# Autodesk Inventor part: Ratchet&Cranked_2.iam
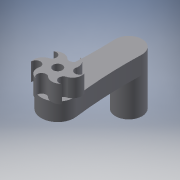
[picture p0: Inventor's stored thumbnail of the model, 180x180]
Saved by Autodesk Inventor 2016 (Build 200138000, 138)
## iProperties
Created: 2013-11
Part Number: Ratchet&Cranked_2.iam
Material: Generic
Document SubType Name: Modeling
Designer: 603839
Density: 1 g/cm^3
Appearance: Default
Mass: 4.07709 g
Surface Area: 25.4645 cm^2
Volume: 4.07709 cm^3
Author: 603839
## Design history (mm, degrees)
sketch "Sketch1" dims "d0" = 30.48
  geometry: L1 (0, 15.24)-(13.198, 7.62); L2 (13.198, 7.62)-(13.198, -7.62); L3 (13.198, -7.62)-(0, -15.24); L4 (0, -15.24)-(-13.198, -7.62); L5 (-13.198, -7.62)-(-13.198, 7.62); L6 (-13.198, 7.62)-(0, 15.24); 3 further points
  constraints: 12 end point, 2 coincident, 1 vertical alignment, 15 other
extrude "Extrusion1" new body sketch "Sketch1" distance "d1" = 12.7; taper "d2" = 0 deg
sketch "Sketch2"
  geometry: L1 (-13.198, -7.62)-(0, -15.24) reference; L2 (0, -15.24)-(13.198, -7.62) reference; L3 (13.198, -7.62)-(13.198, 7.62) reference; L4 (13.198, 7.62)-(0, 15.24) reference; L5 (0, 15.24)-(-13.198, 7.62) reference; L6 (-13.198, 7.62)-(-13.198, -7.62) reference; L7 (-13.198, 7.62)-(13.198, -7.62); L8 (13.198, 7.62)-(-13.198, -7.62); L9 (0, -15.24)-(0, 15.24); L10 (0, 15.24)-(0, 11.43); L11 (13.198, 7.62)-(9.899, 5.715); L12 (13.198, -7.62)-(9.899, -5.715); L13 (0, -15.24)-(0, -11.43); L14 (-13.198, -7.62)-(-9.899, -5.715); L15 (-13.198, 7.62)-(-9.899, 5.715); L16 (-13.198, -7.62)-(-9.899, -5.715); C1 r 3.3 at (0, 11.43); C2 r 3.3 at (9.899, 5.715); C3 r 3.3 at (-9.899, 5.715); C4 r 3.3 at (-9.899, -5.715); C5 r 3.3 at (0, -11.43); C6 r 3.3 at (9.899, -5.715); 1 further point
  constraints: 20 end point, 6 centre point, 6 coincident, 6 point on line, 6 tangent, 3 parallel, 1 collinear
  dimensions: "d4" = 3.81 distance of L4.end L10.end; "d5" = 3.81 distance of L3.end L11.end; "d6" = 3.81 distance of L2.end L12.end; "d7" = 3.81 distance of L1.end L13.end; "d8" = 3.81 distance of L5.end L15.end; "d9" = 3.81 distance of L1.start L14.end
extrude "Extrusion2" cut sketch "Sketch2" distance "d10" = 12.7; taper "d11" = 0 deg
sketch "Sketch3"
  geometry: L1 (-13.198, 5.715)-(-13.198, -5.715) reference; L2 (-11.548, -8.573)-(-1.65, -14.287) reference; L3 (1.65, -14.287)-(11.548, -8.572) reference; L4 (13.198, -5.715)-(13.198, 5.715) reference; L5 (11.548, 8.573)-(1.65, 14.288) reference; L6 (-1.65, 14.287)-(-11.548, 8.572) reference; L7 (11.548, -8.572)-(1.65, -14.287); L8 (-1.65, -14.287)-(-11.548, -8.573); L9 (-13.198, -5.715)-(-13.198, 5.715); L10 (-11.548, 8.572)-(-1.65, 14.287); L11 (1.65, 14.288)-(11.548, 8.573); L12 (13.198, 5.715)-(13.198, -5.715); A1 r 3.3 centre (-9.899, 5.715) between (-13.198, 5.715) and (-11.548, 8.572) reference; A2 r 3.3 centre (-9.899, -5.715) between (-11.548, -8.573) and (-13.198, -5.715) reference; A3 r 3.3 centre (0, -11.43) between (1.65, -14.287) and (-1.65, -14.287) reference; A4 r 3.3 centre (9.899, -5.715) between (13.198, -5.715) and (11.548, -8.572) reference; A5 r 3.3 centre (9.899, 5.715) between (11.548, 8.573) and (13.198, 5.715) reference; A6 r 3.3 centre (0, 11.43) between (-1.65, 14.287) and (1.65, 14.288) reference; A7 r 10.846 centre (-6.125, -0.821) between (0, 8.13) and (-11.548, 8.572); A8 r 10.846 centre (-3.773, 4.894) between (7.041, 4.065) and (1.65, 14.288); A9 r 10.846 centre (2.352, 5.715) between (7.041, -4.065) and (13.198, 5.715); A10 r 10.846 centre (6.125, 0.821) between (0, -8.13) and (11.548, -8.572); A11 r 10.846 centre (3.773, -4.894) between (-7.041, -4.065) and (-1.65, -14.287); A12 r 10.846 centre (-2.352, -5.715) between (-7.041, 4.065) and (-13.198, -5.715); A13 r 3.3 centre (-9.899, -5.715) between (-11.548, -8.573) and (-6.864, -7.011); A14 r 3.3 centre (-9.899, 5.715) between (-13.198, 5.715) and (-9.504, 2.439); A15 r 3.3 centre (0, 11.43) between (-1.65, 14.287) and (-2.64, 9.45); A16 r 3.3 centre (9.899, 5.715) between (11.548, 8.573) and (6.864, 7.011); A17 r 3.3 centre (9.899, -5.715) between (13.198, -5.715) and (9.504, -2.439); A18 r 3.3 centre (0, -11.43) between (1.65, -14.287) and (2.64, -9.45); 1 further point
  constraints: 42 point on circle, 18 tangent, 12 centre point, 12 end point, 6 concentric, 2 equal length, 1 point on line
extrude "Extrusion3" cut sketch "Sketch3" distance "d12" = 12.7; taper "d13" = 0 deg
sketch "Sketch4"
  geometry: L1 (-1.65, -14.287)-(0, -15.24) reference; L2 (0, -15.24)-(13.198, -7.62) reference; A1 r 3.3 centre (0, -11.43) between (-1.65, -14.287) and (1.65, -14.287) reference; 1 further point
sketch "Sketch5"
  geometry: L1 (11.548, -8.572)-(13.198, -7.62) reference; L2 (13.198, -7.62)-(13.198, 7.62) reference; A1 r 3.3 centre (9.899, -5.715) between (11.548, -8.572) and (13.198, -5.715) reference; 1 further point
sketch "Sketch6"
  geometry: L1 (13.198, 5.715)-(13.198, 7.62) reference; L2 (13.198, 7.62)-(0, 15.24) reference; A1 r 3.3 centre (9.899, 5.715) between (13.198, 5.715) and (11.548, 8.573) reference; 1 further point
sketch "Sketch7"
  geometry: L1 (1.65, 14.288)-(0, 15.24) reference; L2 (0, 15.24)-(-13.198, 7.62) reference; A1 r 3.3 centre (0, 11.43) between (1.65, 14.288) and (-1.65, 14.287) reference; 1 further point
sketch "Sketch8"
  geometry: L1 (-11.548, 8.572)-(-13.198, 7.62) reference; L2 (-13.198, 7.62)-(-13.198, -7.62) reference; A1 r 3.3 centre (-9.899, 5.715) between (-11.548, 8.572) and (-13.198, 5.715) reference; 1 further point
sketch "Sketch9"
  geometry: L1 (-13.198, -5.715)-(-13.198, -7.62) reference; L2 (-13.198, -7.62)-(0, -15.24) reference; A1 r 3.3 centre (-9.899, -5.715) between (-13.198, -5.715) and (-11.548, -8.573) reference; 1 further point
extrude "Extrusion4" cut sketch "Sketch9" distance "d14" = 12.7; taper "d15" = 0 deg
extrude "Extrusion5" cut sketch "Sketch4" distance "d16" = 12.7; taper "d17" = 0 deg
extrude "Extrusion6" cut sketch "Sketch5" distance "d18" = 12.7; taper "d19" = 0 deg
extrude "Extrusion7" cut sketch "Sketch6" distance "d20" = 12.7; taper "d21" = 0 deg
extrude "Extrusion8" cut sketch "Sketch7" distance "d22" = 12.7; taper "d23" = 0 deg
extrude "Extrusion9" cut sketch "Sketch8" distance "d24" = 12.7; taper "d25" = 0 deg
sketch "Sketch10"
  geometry: C1 r 3.175 at (0, 0); 1 further point
  constraints: 1 centre point, 1 coincident
  dimensions: "d26" = 6.35 diameter of C1 (derived)
extrude "Extrusion10" cut sketch "Sketch10" distance "d27" = 12.7; taper "d28" = 0 deg
sketch "Sketch11"
  geometry: A1 r 10.846 centre (2.352, 5.715) between (9.504, -2.439) and (13.198, 5.715) reference; A2 r 10.846 centre (-3.773, 4.894) between (6.864, 7.011) and (1.65, 14.288) reference; A3 r 10.846 centre (-6.125, -0.821) between (-2.64, 9.45) and (-11.548, 8.572) reference; A4 r 10.846 centre (-2.352, -5.715) between (-9.504, 2.439) and (-13.198, -5.715) reference; A5 r 10.846 centre (3.773, -4.894) between (-6.864, -7.011) and (-1.65, -14.287) reference; A6 r 10.846 centre (6.125, 0.821) between (2.64, -9.45) and (11.548, -8.572) reference; A7 r 6.604 centre (-6.928, -3.642) between (-9.504, 2.439) and (-13.198, -5.715); A8 r 6.604 centre (-6.618, 4.179) between (-2.64, 9.45) and (-11.548, 8.572); A9 r 6.604 centre (0.31, 7.821) between (6.864, 7.011) and (1.65, 14.288); A10 r 6.604 centre (6.928, 3.642) between (9.504, -2.439) and (13.198, 5.715); A11 r 6.604 centre (6.618, -4.179) between (2.64, -9.45) and (11.548, -8.572); A12 r 6.604 centre (-0.31, -7.821) between (-6.864, -7.011) and (-1.65, -14.287)
  constraints: 12 point on circle, 6 centre point
  dimensions: "d29" = 6.604 radius of A7 (derived); "d30" = 6.604 radius of A8 (derived); "d31" = 6.604 radius of A9 (derived); "d32" = 6.604 radius of A10 (derived); "d33" = 6.604 radius of A11 (derived); "d34" = 6.604 radius of A12 (derived)
extrude "Extrusion11" join sketch "Sketch11" distance "d35" = 12.7; taper "d36" = 0 deg
hole "Hole1" diameter "d39" = 6.604; stored, may be unused: countersink angle "d43" = 82 deg, drill point angle "d45" = 0 deg; dims "d40" = 19.05, "d41" = 9.525, "d42" = 6.35, "d44" = 25.4, "d46" = 25.4, "d47" = 25.4
sketch "Sketch17"
  geometry: A1 r 11.738 centre (0, 0) between (11.643, -1.493) and (-11.653, -1.411); A2 r 9.525 centre (-0.179, -50.8) between (-9.696, -50.413) and (9.341, -50.48); A3 r 304.8 centre (-314.245, -38.039) between (-9.696, -50.413) and (-11.653, -1.411); A4 r 304.8 centre (313.969, -40.25) between (11.643, -1.493) and (9.341, -50.48); 1 further point
  constraints: 16 point on circle, 4 centre point, 4 tangent, 1 coincident
  dimensions: "d61" = 19.05 diameter of A2; "d63" = 304.8 radius of A3; "d64" = 304.8 radius of A4; "d69" = 50.8 vertical distance of point (0, 0) A2.centre
extrude "Extrusion15" join sketch "Sketch17" distance "d65" = 12.7; taper "d66" = 0 deg
sketch "Sketch19"
  geometry: C1 r 9.525 at (-0.179, -50.8); A1 r 9.525 centre (-0.179, -50.8) between (-9.696, -50.413) and (9.341, -50.48) reference; 1 further point
  constraints: 1 centre point, 1 coincident
extrude "Extrusion16" join sketch "Sketch19" distance "d67" = 25.4; taper "d68" = 0 deg
body "Solid1"
